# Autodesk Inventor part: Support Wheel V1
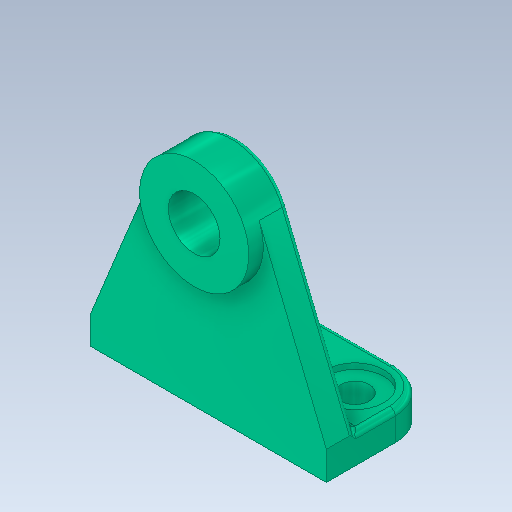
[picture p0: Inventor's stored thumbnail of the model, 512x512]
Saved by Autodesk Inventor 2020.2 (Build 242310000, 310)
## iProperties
Created: 2018-06
Part Number: Support Wheel V1
Material: Iron, Cast
Document SubType Name: Modeling
Designer: Power User
Density: 7.15 g/cm^3
Appearance: Aluminum - Polished(1)
Mass: 471.804 g
Surface Area: 175.665 cm^2
Volume: 65.9865 cm^3
Author: Power User
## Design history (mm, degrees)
sketch "Sketch1"
  geometry: L1 (0, 0)-(0, 60); L2 (-41, 0)-(-41, 10); L3 (-41, 10)-(-17.584, 67.199); L4 (-41, 0)-(0, 0); L5 (41, 10)-(17.584, 67.199); L6 (41, 0)-(41, 10); L7 (41, 0)-(0, 0); L8 (-41, 10)-(41, 10); A1 r 19 centre (0, 60) between (-17.584, 67.199) and (17.584, 67.199)
  constraints: 16 end point, 3 symmetric about line, 3 vertical, 2 point on circle, 1 centre point, 1 coincident, 1 horizontal, 1 tangent
  dimensions: "d0" = 60 distance of L1.start L1.end; "d1" = 38 diameter of A1; "d2" = 10 distance of L2.start L2.end; "d3" = 82 diameter of L2 L1
extrude "Extrusion2" new body sketch "Sketch1" distance "d7" = 10; taper "d8" = 0 deg
extrude "Extrusion3" join sketch "Sketch1" distance "d9" = 38; taper "d10" = 0 deg
extrude "Extrusion4" join sketch "Sketch1" distance "d11" = 5; taper "d12" = 0 deg
sketch "Sketch2"
  geometry: C1 r 19 at (0, 0) reference; 2 further points
  constraints: 1 coincident
hole "Hole1" sketch "Sketch2" at (0, 0) diameter "d13" = 18; stored, may be unused: countersink angle "d17" = 90 deg, drill point angle "d19" = 118 deg; dims "d14" = 6, "d15" = 4, "d16" = 2, "d18" = 8
fillet "Fillet1" dims "d20" = 14
node "Hole4"
sketch "Sketch3"
  geometry: A1 r 14 centre (14, 14) between (14, 28) and (0, 14) reference; A2 r 14 centre (68, 14) between (82, 14) and (68, 28) reference; 3 further points
  constraints: 2 coincident
hole "Hole2" sketch "Sketch3" at (14, 14), (68, 14) diameter "d21" = 10; stored, may be unused: countersink angle "d25" = 90 deg, drill point angle "d27" = 118 deg; dims "d22" = 6, "d23" = 20, "d24" = 2, "d26" = 8
fillet "Fillet2" dims "d28" = 2
body "Solid2"
sketch "Sketch4"
  geometry: 1 further point
hole "Hole3" sketch "Sketch4" diameter "d29" = 9; stored, may be unused: countersink angle "d33" = 90 deg, drill point angle "d35" = 0 deg; dims "d30" = 6, "d31" = 4, "d32" = 2, "d34" = 8
